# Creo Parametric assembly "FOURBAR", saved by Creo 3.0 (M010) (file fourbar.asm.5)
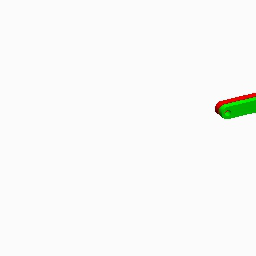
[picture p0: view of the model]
Units: millimeter Kilogram Sec (mmKs); MM, KILOGRAM, SECS

Other parameters: ROTATION1_STATIC_FRICTION, ROTATION1_KINETIC_FRICTION, ROTATION1_CONTACT_RADIUS, ROTATION1_RESTITUTION, ROTATION1_MINIMUM_LIMIT, ROTATION1_MAXIMUM_LIMIT, ROTATION1_ZERO_POSITION

Created from: MMKS_ASM_DESIGN.ASM

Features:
  1. datum plane "ASM_RIGHT"
  2. datum plane "ASM_TOP"
  3. datum plane "ASM_FRONT"
  4. coordinate system
  5. component "BAR1"
  6. component "BAR2"
  7. component "BAR3"
  8. component "BAR4"
  9. coordinate system "ACS0"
